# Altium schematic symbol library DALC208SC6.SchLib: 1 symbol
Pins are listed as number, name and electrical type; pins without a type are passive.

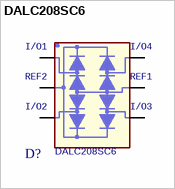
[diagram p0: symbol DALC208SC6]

## DALC208SC6
designator D?
footprint ST_SOT23-6L
pins: 1 I/O 1, 2 REF 2, 3 I/O 2, 4 I/O 3, 5 REF 1, 6 I/O 4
